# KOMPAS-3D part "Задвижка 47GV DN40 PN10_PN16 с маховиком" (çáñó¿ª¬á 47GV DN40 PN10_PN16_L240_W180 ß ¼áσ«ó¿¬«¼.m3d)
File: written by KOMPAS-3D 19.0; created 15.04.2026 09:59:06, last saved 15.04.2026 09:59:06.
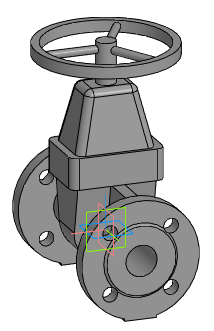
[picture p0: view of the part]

Document properties: Автор: Евгений; Полное имя файла: Z:\3.Личные\kachalov\3d для проектировщиков\2.1 Тип 47GV, 47GV.Z\Задвижка 47GV_DN40-DN600\stp_Задвижка 47GV\Задвижка 47GV DN40 PN10_PN16_L240_W180 с маховиком.m3d

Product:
- Part/product: Задвижка 47GV DN40 PN10_PN16 с маховиком

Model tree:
1. Операция без истории:1  (labels: Задвижка 47GV DN40 PN10_PN16 с маховиком)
